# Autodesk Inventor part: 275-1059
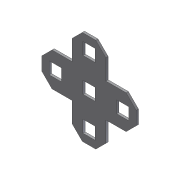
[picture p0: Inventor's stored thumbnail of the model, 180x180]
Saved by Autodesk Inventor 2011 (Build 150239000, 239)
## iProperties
Company: Autodesk Inc.
Created: 2005-07
Part Number: 275-1059
Document SubType Name: Modeling
Designer: Autodesk Inc.
Density: 1 g/cm^3
Catalog Web Link: http://www.vexrobotics.com/products/accessories/structure/plus-gusset.html
Description: Generic gusset for strengthening flat joints. Can be easily cut into a "T" gusset or an "L" gusset.
Vendor: Innovation First, Inc.
Author: Autodesk Inc.
Title: VEX Robotics Kit of Parts
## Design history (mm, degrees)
sketch "Sketch1"
  geometry: L1 (20.926, 6.768)-(20.926, 1.688); L2 (-14.634, 1.688)-(-14.634, 6.768); L3 (0.606, 22.008)-(5.686, 22.008); L4 (5.686, -13.552)-(0.606, -13.552); L5 (-3.204, -9.742)-(-3.204, -2.122); L6 (-3.204, 10.578)-(-3.204, 18.198); L7 (-10.824, 10.578)-(-3.204, 10.578); L8 (9.496, 10.578)-(17.116, 10.578); L9 (17.116, -2.122)-(9.496, -2.122); L10 (-3.204, -2.122)-(-10.824, -2.122); L11 (9.496, 18.198)-(9.496, 10.578); L12 (9.496, -2.122)-(9.496, -9.742); L13 (-3.204, 18.198)-(0.606, 22.008); L14 (5.686, 22.008)-(9.496, 18.198); L15 (17.116, 10.578)-(20.926, 6.768); L16 (20.926, 1.688)-(17.116, -2.122); L17 (9.496, -9.742)-(5.686, -13.552); L18 (-3.204, -9.742)-(0.606, -13.552); L19 (-14.634, 1.688)-(-10.824, -2.122); L20 (-14.634, 6.768)-(-10.824, 10.578); L21 (0.86, 19.214)-(5.432, 19.214); L22 (5.432, 19.214)-(5.432, 14.642); L23 (5.432, 14.642)-(0.86, 14.642); L24 (0.86, 14.642)-(0.86, 19.214); L25 (-11.84, 6.514)-(-7.268, 6.514); L26 (-7.268, 6.514)-(-7.268, 1.942); L27 (-7.268, 1.942)-(-11.84, 1.942); L28 (-11.84, 1.942)-(-11.84, 6.514); L29 (0.86, -6.186)-(5.432, -6.186); L30 (5.432, -6.186)-(5.432, -10.758); L31 (5.432, -10.758)-(0.86, -10.758); L32 (0.86, -10.758)-(0.86, -6.186); L33 (13.56, 6.514)-(18.132, 6.514); L34 (18.132, 6.514)-(18.132, 1.942); L35 (18.132, 1.942)-(13.56, 1.942); L36 (13.56, 1.942)-(13.56, 6.514); L37 (0.86, 6.514)-(5.432, 6.514); L38 (5.432, 6.514)-(5.432, 1.942); L39 (5.432, 1.942)-(0.86, 1.942); L40 (0.86, 1.942)-(0.86, 6.514); 8 further points
  constraints: 80 end point, 20 parallel, 16 point on line, 9 perpendicular, 8 horizontal, 4 collinear
  dimensions: "d0" = 35.56 distance between parallel lines of L1 L2; "d1" = 35.56 distance between parallel lines of L4 L3; "d2" = 12.7 distance of point (-3.204, 22.008) point (9.496, 22.008); "d3" = 12.7 distance of point (-14.634, -2.122) point (-14.634, 10.578); "d4" = 12.7 distance of point (20.926, 10.578) point (20.926, -2.122); "d5" = 12.7 distance of point (9.496, -13.552) point (-3.204, -13.552); "d6" = 11.43 distance of L6.start point (-3.204, 22.008); "d7" = 11.43 distance of point (-3.204, -13.552) L5.end (derived); "d8" = 11.43 distance of L9.end point (9.496, -13.552); "d9" = 11.43 distance of point (-14.634, 10.578) L6.start; "d10" = 3.81 distance of L6.end point (-3.204, 22.008); "d11" = 3.81 distance of L3.start point (-3.204, 22.008) (= d10); "d12" = 3.81 distance of L3.end point (9.496, 22.008) (= d10); "d13" = 3.81 distance of L11.start point (9.496, 22.008) (= d12); "d14" = 3.81 distance of L8.end point (20.926, 10.578) (= d10); "d15" = 3.81 distance of L1.start point (20.926, 10.578) (= d14); "d16" = 3.81 distance of L1.end point (20.926, -2.122) (= d10); "d17" = 3.81 distance of L9.start point (20.926, -2.122) (= d16); "d18" = 3.81 distance of L12.end point (9.496, -13.552) (= d10); "d19" = 3.81 distance of L4.start point (9.496, -13.552) (= d18); "d20" = 3.81 distance of L5.start point (-3.204, -13.552) (= d10); "d21" = 3.81 distance of L4.end point (-3.204, -13.552) (= d20); "d22" = 3.81 distance of L2.start point (-14.634, -2.122) (= d10); "d23" = 3.81 distance of L10.end point (-14.634, -2.122) (= d22); "d24" = 3.81 distance of L2.end point (-14.634, 10.578) (= d10); "d25" = 3.81 distance of L7.start point (-14.634, 10.578) (= d24); "d26" = 4.572 distance of L22.end L23.end; "d27" = 4.572 distance of L23.end L21.start; "d28" = 4.572 distance of L25.end L26.end; "d29" = 4.572 distance of L25.start L25.end; "d30" = 4.572 distance of L37.start L37.end; "d31" = 4.572 distance of L39.end L37.start; "d32" = 4.572 distance of L35.end L33.start; "d33" = 4.572 distance of L34.end L35.end; "d34" = 4.572 distance of L29.start L29.end; "d35" = 4.572 distance of L31.end L29.start; "d36" = 2.794 distance between parallel lines of L2 L28; "d37" = 2.794 distance between parallel lines of L3 L21; "d38" = 2.794 distance between parallel lines of L4 L31; "d39" = 2.794 distance between parallel lines of L1 L34; "d40" = 4.064 distance between parallel lines of L8 L33; "d41" = 4.064 distance between parallel lines of L12 L30; "d42" = 11.43 distance between parallel lines of L5 L2
extrude "Extrusion1" new body sketch "Sketch1" distance "d43" = 0.8382; taper "d44" = 0 deg
body "Solid1"
